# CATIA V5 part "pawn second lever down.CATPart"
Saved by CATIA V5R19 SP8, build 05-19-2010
Part number: pawn second lever down
Bounding box of the stored display mesh (mm): x 39.244 to 54.244, y -6.9 to 31.1, z 13.238 to 27.862
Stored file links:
  G:\EU_thinkMotion\CFAO_2010\MMS_groupe1\MMS_groupe1\A reprendre\gduval\CFAO kinematic ok\pawn second lever down.CATPart
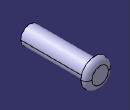
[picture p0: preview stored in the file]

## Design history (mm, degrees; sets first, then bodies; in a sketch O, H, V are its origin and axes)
Body1 (main body)
  Plane1: type Offset, RefPlane zx-plane, Offset 28.1
  Point1: stored without definition
  Sketch1 on Plane1, origin (0, 28.1, 0), H (-1, 0, 0), V (0, 0, 1)
    circle A1 centre (-46.744, 20.55) radius 5
    point P1 (-46.744, 20.55)
    reference projected point E1 (-46.744, 20.55) from Point1
    reference projected point E2 (-46.744, 20.55) from Point1
    radius A1 = 5
    coincidence: E1 P1
    concentricity: A1 E2
  Pad1: profile Sketch1, direction (0, -1, 0), length 35
  Sketch2 on start face of Pad1, origin (0, 28.1, 0), H (-1, 0, 0), V (0, 0, 1)
    circle A1 centre (-46.744, 20.55) radius 7.5
    reference projected circle E1 centre (-46.744, 20.55) radius 5 from Sketch1.A1
    radius A1 = 7.5
    concentricity: A1 E1
  Pad2: profile Sketch2, direction (0, 1, 0), length 3
  Fillet1: radius 3, on edge [face of Pad2 from Sketch2.A1 | end face of Pad2]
